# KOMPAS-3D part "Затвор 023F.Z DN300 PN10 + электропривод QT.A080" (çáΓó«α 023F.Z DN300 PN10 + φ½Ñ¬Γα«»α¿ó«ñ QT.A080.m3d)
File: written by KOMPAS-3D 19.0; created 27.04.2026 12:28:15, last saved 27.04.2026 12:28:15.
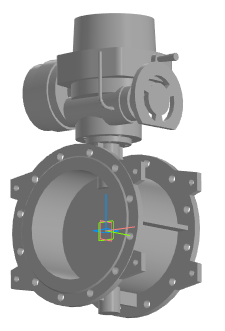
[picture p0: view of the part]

Document properties: Полное имя файла: Затвор 023F.Z DN300 PN10 + электропривод QT.A080.a3d

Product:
- Part/product: Затвор 023F.Z DN300 PN10 + электропривод QT.A080
    Масса: 219.964

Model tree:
1. Операция без истории:1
